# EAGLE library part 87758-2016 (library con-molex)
20 Pin - 2mm Dual Row Single Wafer, Vertical T/H HDR Source: http://www.molex.com/pdm_docs/sd/877580616_sd.pdf
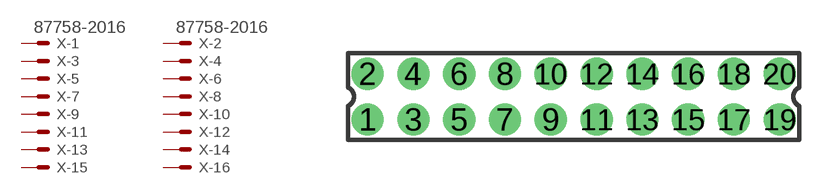
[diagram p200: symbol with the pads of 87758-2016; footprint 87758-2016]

Designator prefix X; gates -1=MV -2=MV -3=M -4=M -5=M -6=M -7=M -8=M -9=M -10=M -11=M -12=M -13=M -14=M -15=M -16=M -17=M -18=M -19=M -20=M

## 87758-2016 (MPN: 87758-2016; OC_FARNELL: 7472374; OC_NEWARK: 25M5677)  [87758-2016]
1  -1:S  pas
2  -2:S  pas
3  -3:S  pas
4  -4:S  pas
5  -5:S  pas
6  -6:S  pas
7  -7:S  pas
8  -8:S  pas
9  -9:S  pas
10  -10:S  pas
11  -11:S  pas
12  -12:S  pas
13  -13:S  pas
14  -14:S  pas
15  -15:S  pas
16  -16:S  pas
17  -17:S  pas
18  -18:S  pas
19  -19:S  pas
20  -20:S  pas

## Footprint 87758-2016 (pad centres in mm)
20 Pin - 2mm Dual Row Single Wafer, Vertical T/H HDR Source: http://www.molex.com/pdm_docs/sd/877580616_sd.pdf
drill 0.9 pad 1.27 round: 1 -9,-1; 2 -9,1; 3 -7,-1; 4 -7,1; 5 -5,-1; 6 -5,1; 7 -3,-1; 8 -3,1; 9 -1,-1; 10 -1,1; 11 1,-1; 12 1,1; 13 3,-1; 14 3,1; 15 5,-1; 16 5,1; 17 7,-1; 18 7,1; 19 9,-1; 20 9,1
